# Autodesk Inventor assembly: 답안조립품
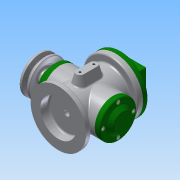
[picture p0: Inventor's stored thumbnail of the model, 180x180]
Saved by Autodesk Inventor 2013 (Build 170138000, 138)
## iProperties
Created: 2018-02
Part Number: 답안조립품
Document SubType Name: Assembly
Designer: Administrator
Author: Administrator
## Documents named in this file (18)
- C:\Users\Administrator\Desktop\480208V1008\답안조립품.iam
- C:\Users\Administrator\Desktop\480208V1008\본체.ipt
- C:\Users\Administrator\Desktop\480208V1008\E-링.ipt
- C:\Users\Administrator\Desktop\480208V1008\V-벨트풀리.ipt
- C:\Users\Administrator\Desktop\480208V1008\덮개.ipt
- C:\Users\Administrator\Desktop\480208V1008\뒤커버.ipt
- C:\Users\Administrator\Desktop\480208V1008\링크.ipt
- C:\Users\Administrator\Desktop\480208V1008\베어링 17 x 40 x 12.ipt
- C:\Users\Administrator\Desktop\480208V1008\볼트 M4 x 8.ipt
- C:\Users\Administrator\Desktop\480208V1008\볼트 M4 x 10.ipt
- C:\Users\Administrator\Desktop\480208V1008\슬라이더.ipt
- C:\Users\Administrator\Desktop\480208V1008\앞커버.ipt
- C:\Users\Administrator\Desktop\480208V1008\오일 실 17 30 8.ipt
- C:\Users\Administrator\Desktop\480208V1008\와셔 4x16.ipt
- C:\Users\Administrator\Desktop\480208V1008\클레비스 핀 6 x 22.ipt
- 클레비스 핀 6 x 22.ipt
- C:\Users\Administrator\Desktop\480208V1008\키 4 x 4 x 12.ipt
- C:\Users\Administrator\Desktop\480208V1008\편심축.ipt
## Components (2 placed, 2 different names)
1. E-링:1
2. V-벨트풀리:1
